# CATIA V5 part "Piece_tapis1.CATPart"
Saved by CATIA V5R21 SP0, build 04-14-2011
Part number: Piece tapis1
Bounding box of the stored display mesh (mm): x -17 to 17, y -17 to 17, z 0 to 4.53
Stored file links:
  C:\Users\Raphael\Documents\Imprimante 3D\Tapis voiture Hyundai Elantra 2014\Piece tapis1.CATPart
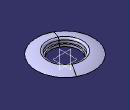
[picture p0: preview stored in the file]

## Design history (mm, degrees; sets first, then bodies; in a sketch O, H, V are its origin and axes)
Body1 (main body)
  Sketch1 on yz-plane, origin (0, 0, 0), H (0, 1, 0), V (0, 0, 1)
    line L1 (-8.5, 0) -> (-8.5, 1.91)
    point P1 (-8.5, 0)
    line L2 (-8.5, 1.91) -> (-9.25, 1.91)
    line L3 (-9.25, 1.91) -> (-9.25, 4.63)
    point P4 (-9.25, 4.63)
    point P5 (-17, 2.63)
    line L4 (-17, 2.63) -> (-10.115, 2.63)
    line L5 (-10.115, 2.63) -> (-10.115, 0)
    point P7 (-10.115, 0)
    line L6 (-10.115, 0) -> (-8.5, 0)
    axis line L7 (0, 63.1718) -> (0, -56.9962)
    point P8 (0, 63.1718)
    arc A1 centre (-7.7194, -17.3167) radius 22 from (-17, 2.63) to (-9.25, 4.63) cw
    "Radius" L7 L5 = 10.115
    distance L6 L4 = 2.63
    distance L2 P4 = 2.72
    "Radius" L1 L7 = 8.5
    "Radius" L3 L7 = 9.25
    distance P4 L6 = 4.63
    "Radius" P5 L7 = 17
    radius A1 = 22
    coincidence: P1 H, P7 H, P8 V
    vertical: L1 V, L3 V, L5 V, L7 V
    horizontal: L2 H, L4 H, L6 H
  Shaft1: profile Sketch1, axis Sketch1.L7, angle 360
  Fillet1: radius 1, on edge [face of Shaft1 from Sketch1.L3 | face of Shaft1 from Sketch1.A1]
  Chamfer1: length 1, angle 30, on edge [face of Shaft1 from Sketch1.L6 | face of Shaft1 from Sketch1.L1]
